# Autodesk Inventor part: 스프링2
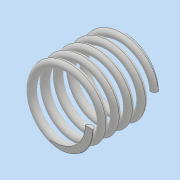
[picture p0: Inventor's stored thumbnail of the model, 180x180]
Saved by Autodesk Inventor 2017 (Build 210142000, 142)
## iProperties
Part Number: 스프링2
Material: 일반
Document SubType Name: Modeling
Designer: MRC
Density: 1 g/cm^3
Appearance: 기본값
Author: MRC
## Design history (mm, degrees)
sketch "스케치1"
  geometry: L1 (0, 0)-(0, 17.5); L2 (0, 0)-(8.5, 0); L3 (0, 17.5)-(8.5, 17.5); C1 r 1 at (8.5, 0)
  constraints: 6 end point, 1 centre point, 1 coincident, 1 horizontal, 1 vertical, 1 vertical alignment
  dimensions: "d0" = 17.5 distance of L1.start L1.end (derived); "d1" = 17 diameter of L2.end L1; "d2" = 2 diameter of C1
feature "코일1" pitch "d3" = 10; turns "d5" = 5; dims "d4" = 17.5 (= d0), "d6" = 0, angle "d7" = 90 deg, angle "d8" = 90 deg, "d9" = 0, "d10" = 0
sketch "스케치2"
  geometry: L1 (17.5, 17.5)-(0, 17.5); L2 (0, 17.5)-(0, -17.5); L3 (0, -17.5)-(17.5, -17.5); L4 (17.5, -17.5)-(17.5, 17.5); 2 further points
  constraints: 8 end point, 2 parallel, 1 coincident, 1 horizontal, 1 midpoint, 1 perpendicular
  dimensions: "d11" = 17.5 distance of L2.end L3.end (= d0); "d12" = 35 distance between parallel lines of L1 L3
extrude "돌출2" sketch "스케치2" stored distance "d15" = 0; taper "d16" = 0 deg
node "솔리드1"
